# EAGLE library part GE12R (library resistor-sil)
SIL RESISTOR
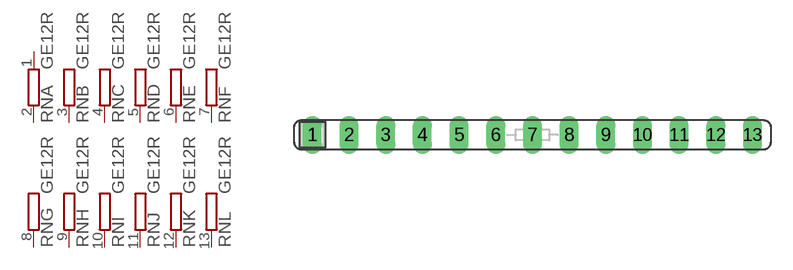
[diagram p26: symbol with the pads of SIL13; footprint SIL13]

Designator prefix RN; gates A=R-NV B=R-NV1 C=R-NV1 D=R-NV1 E=R-NV1 F=R-NV1 G=R-NV1 H=R-NV1 I=R-NV1 J=R-NV1 K=R-NV1 L=R-NV1

## GE12R (OC_FARNELL: unknown; OC_NEWARK: unknown)  [SIL13]
1  A:1  pas
2  A:2  pas
3  B:2  pas
4  C:2  pas
5  D:2  pas
6  E:2  pas
7  F:2  pas
8  G:2  pas
9  H:2  pas
10  I:2  pas
11  J:2  pas
12  K:2  pas
13  L:2  pas

## Footprint SIL13 (pad centres in mm)
Single In Line
drill 0.813 long: 1 -15.24,0; 2 -12.7,0; 3 -10.16,0; 4 -7.62,0; 5 -5.08,0; 6 -2.54,0; 7 0,0; 8 2.54,0; 9 5.08,0; 10 7.62,0; 11 10.16,0; 12 12.7,0; 13 15.24,0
